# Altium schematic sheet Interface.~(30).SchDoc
size A4
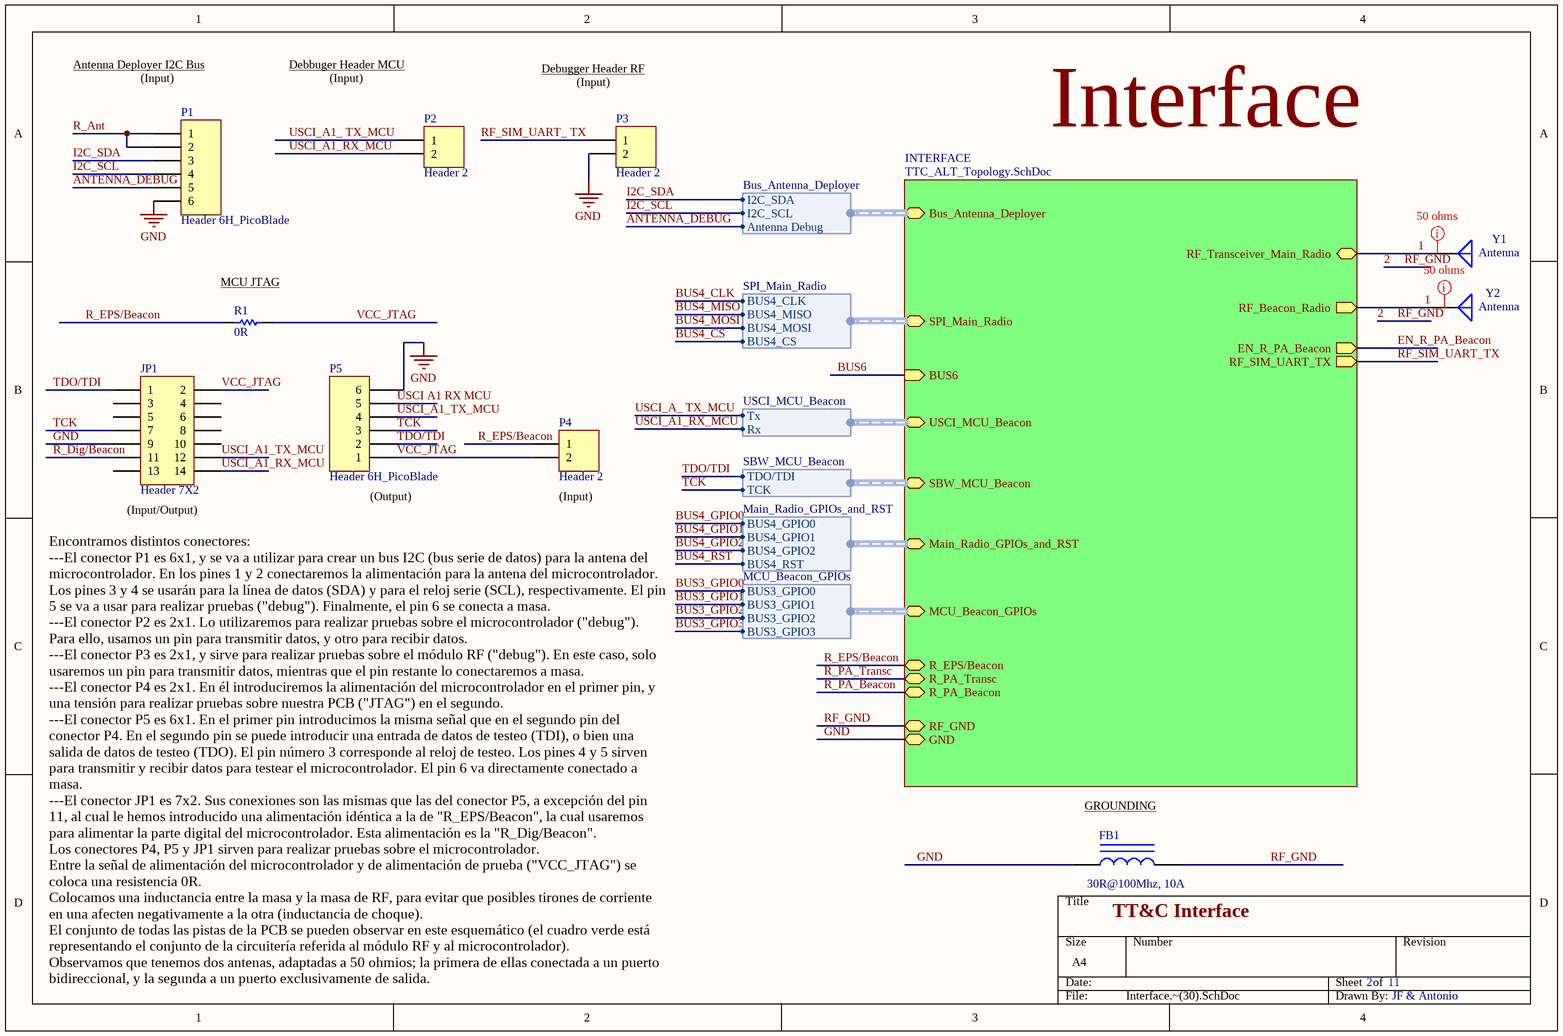
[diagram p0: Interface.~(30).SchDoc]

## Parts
FB1  value 30R@100Mhz, 10A  [INDC3216]
JP1  Header 7X2  [HDR2X7]
P1  Header 6H_PicoBlade  [HDR1X6H]
P2  Header 2  [HDR1X2]
P3  Header 2  [HDR1X2]
P4  Header 2  [HDR1X2]
P5  Header 6H_PicoBlade  [HDR1X6H]
R1  0R  [R]
Y1  Antenna  [PIN1]
Y2  Antenna  [PIN1]

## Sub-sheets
INTERFACE = TTC_ALT_Topology.SchDoc: RF_Transceiver_Main_Radio, RF_Beacon_Radio (out), EN_R_PA_Beacon (out), RF_SIM_UART_TX (out), Bus_Antenna_Deployer (harness Bus_Antenna_Deployer), SPI_Main_Radio (harness SPI_Main_Radio), BUS6 (in), Main_Radio_GPIOs_and_RST (harness Main_Radio_GPIOs_and_RST), USCI_MCU_Beacon (harness USCI_MCU_Beacon), MCU_Beacon_GPIOs (harness MCU_Beacon_GPIOs), R_EPS/Beacon, R_PA_Transc, R_PA_Beacon, RF_GND, GND, SBW_MCU_Beacon (harness SBW_MCU_Beacon)

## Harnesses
Bus_Antenna_Deployer: I2C_SDA, I2C_SCL, Antenna Debug
SPI_Main_Radio: BUS4_CLK, BUS4_MISO, BUS4_MOSI, BUS4_CS
SBW_MCU_Beacon: TDO/TDI, TCK
Main_Radio_GPIOs_and_RST: BUS4_GPIO0, BUS4_GPIO1, BUS4_GPIO2, BUS4_RST
MCU_Beacon_GPIOs: BUS3_GPIO0, BUS3_GPIO1, BUS3_GPIO2, BUS3_GPIO3
USCI_MCU_Beacon: Tx, Rx

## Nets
GND: FB1.1 JP1.9 P1.6 P3.2 P5.6 ; sheet INTERFACE/GND
1: Y1.1(A) Y2.1(A) ; sheet INTERFACE/RF_Transceiver_Main_Radio, sheet INTERFACE/RF_Beacon_Radio
2: FB1.2 ; sheet INTERFACE/RF_GND  [also labelled RF_GND]
ANTENNA_DEBUG: P1.5 ; sheet INTERFACE/Bus_Antenna_Deployer.Antenna Debug
I2C_SCL: P1.4 ; sheet INTERFACE/Bus_Antenna_Deployer.I2C_SCL
I2C_SDA: P1.3 ; sheet INTERFACE/Bus_Antenna_Deployer.I2C_SDA
R_Ant: P1.1 P1.2
R_Dig/Beacon: JP1.11
R_EPS/Beacon: P4.1 R1.1 ; sheet INTERFACE/R_EPS/Beacon
RF_SIM_UART_ TX: P3.1
TCK: JP1.7 P5.3 ; sheet INTERFACE/SBW_MCU_Beacon.TCK
TDO/TDI: JP1.1 P5.2 ; sheet INTERFACE/SBW_MCU_Beacon.TDO/TDI
USCI A1 RX MCU: P5.5
USCI_A1_ TX_MCU: P2.1
USCI_A1_RX_MCU: JP1.14 P2.2 ; sheet INTERFACE/USCI_MCU_Beacon.Rx
USCI_A1_TX_MCU: JP1.12 P5.4
VCC_JTAG: JP1.2 P4.2 P5.1 R1.2

Not connected (* = marked no-connect by the designer): JP1 3 4 5 6 8 10 13

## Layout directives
mark named 50 ohms: (no net found under the mark)

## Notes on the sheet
- Antenna Deployer I2C Bus
- (near P1) (Input)
- Debbuger Header MCU
- (Input)
- Debugger Header RF
- (near P3) (Input)
- Interface
- (near R1) MCU JTAG
- (near JP1) (Input/Output)
- (near P5) (Output)
- (near P4) (Input)
- (near FB1) GROUNDING
- (near FB1) TT&C Interface
- Encontramos distintos conectores:
  ---El conector P1 es 6x1, y se va a utilizar para crear un bus I2C (bus serie de datos) para la antena del microcontrolador. En los pines 1 y 2 conectaremos la alimentación para la antena del microcontrolador. Los pines 3 y 4 se usarán para la línea de datos (SDA) y para el reloj serie (SCL), respectivamente. El pin 5 se va a usar para realizar pruebas ("debug"). Finalmente, el pin 6 se conecta a masa.
  ---El conector P2 es 2x1. Lo utilizaremos para realizar pruebas sobre el microcontrolador ("debug"). Para ello, usamos un pin para transmitir datos, y otro para recibir datos.
  ---El conector P3 es 2x1, y sirve para realizar pruebas sobre el módulo RF ("debug"). En este caso, solo usaremos un pin para transmitir datos, mientras que el pin restante lo conectaremos a masa.
  ---El conector P4 es 2x1. En él introduciremos la alimentación del microcontrolador en el primer pin, y una tensión para realizar pruebas sobre nuestra PCB ("JTAG") en el segundo.
  ---El conector P5 es 6x1. En el primer pin introducimos la misma señal que en el segundo pin del conector P4. En el segundo pin se puede introducir una entrada de datos de testeo (TDI), o bien una salida de datos de testeo (TDO). El pin número 3 corresponde al reloj de testeo. Los pines 4 y 5 sirven para transmitir y recibir datos para testear el microcontrolador. El pin 6 va directamente conectado a masa.
  ---El conector JP1 es 7x2. Sus conexiones son las mismas que las del conector P5, a excepción del pin 11, al cual le hemos introducido una alimentación idéntica a la de "R_EPS/Beacon", la cual usaremos para alimentar la parte digital del microcontrolador. Esta alimentación es la "R_Dig/Beacon".
  Los conectores P4, P5 y JP1 sirven para realizar pruebas sobre el microcontrolador.
  Entre la señal de alimentación del microcontrolador y de alimentación de prueba ("VCC_JTAG") se coloca una resistencia 0R.
  Colocamos una inductancia entre la masa y la masa de RF, para evitar que posibles tirones de corriente en una afecten negativamente a la otra (inductancia de choque).
  El conjunto de todas las pistas de la PCB se pueden observar en este esquemático (el cuadro verde está representando el conjunto de la circuitería referida al módulo RF y al microcontrolador).
  Observamos que tenemos dos antenas, adaptadas a 50 ohmios; la primera de ellas conectada a un puerto bidireccional, y la segunda a un puerto exclusivamente de salida.
- 2
- 11
- JF & Antonio

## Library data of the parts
FB1 = Inductor Iron: Magnetic-Core Inductor
JP1 = Header 7X2: Header, 7-Pin, Dual row
P1 = Header 6H: Header, 6-Pin, Right Angle
P2-P4 = Header 2: Header, 2-Pin
P5 = Header 6H: Header, 6-Pin, Left Angle
R1 = Res1: Resistor
Y1 Y2 = Antenna: Generic Antenna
